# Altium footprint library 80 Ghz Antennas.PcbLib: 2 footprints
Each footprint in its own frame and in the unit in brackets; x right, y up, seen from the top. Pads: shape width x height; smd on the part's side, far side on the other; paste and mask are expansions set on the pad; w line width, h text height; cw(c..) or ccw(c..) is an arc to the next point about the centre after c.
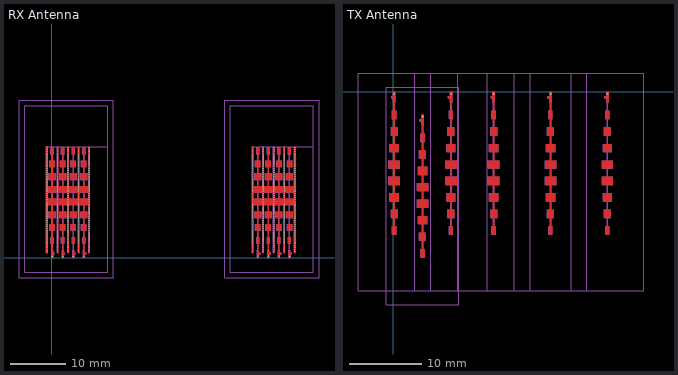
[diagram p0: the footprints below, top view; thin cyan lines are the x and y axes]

## RX Antenna [mm] "RX 80 Ghz Antenna"
pads (8):
  round 0.25 smd: "D1 - RX1"(0.139,0.25) "D1 - RX2"(2.039,0.25) "D1 - RX3"(3.939,0.25) "D1 - RX4"(5.839,0.25) "D2 - RX1"(37.189,0.25) "D2 - RX2"(39.089,0.25) "D2 - RX3"(40.989,0.25) "D2 - RX4"(42.889,0.25)
via 6.789,1.124 diameter 0.2 hole 0.1
via 6.789,1.499 diameter 0.2 hole 0.1
via 6.789,1.874 diameter 0.2 hole 0.1
via 6.789,2.249 diameter 0.2 hole 0.1
via 6.789,2.624 diameter 0.2 hole 0.1
via 6.789,2.999 diameter 0.2 hole 0.1
via 6.789,3.374 diameter 0.2 hole 0.1
via 6.789,5.624 diameter 0.2 hole 0.1
via 6.789,5.249 diameter 0.2 hole 0.1
via 6.789,4.874 diameter 0.2 hole 0.1
via 6.789,4.499 diameter 0.2 hole 0.1
via 6.789,4.124 diameter 0.2 hole 0.1
via 6.789,3.749 diameter 0.2 hole 0.1
via 6.789,7.874 diameter 0.2 hole 0.1
via 6.789,7.499 diameter 0.2 hole 0.1
via 6.789,7.124 diameter 0.2 hole 0.1
via 6.789,6.749 diameter 0.2 hole 0.1
via 6.789,6.374 diameter 0.2 hole 0.1
via 6.789,5.999 diameter 0.2 hole 0.1
via 6.789,10.124 diameter 0.2 hole 0.1
via 6.789,9.749 diameter 0.2 hole 0.1
via 6.789,9.374 diameter 0.2 hole 0.1
via 6.789,8.999 diameter 0.2 hole 0.1
via 6.789,8.624 diameter 0.2 hole 0.1
via 6.789,8.249 diameter 0.2 hole 0.1
via 6.789,12.374 diameter 0.2 hole 0.1
via 6.789,11.999 diameter 0.2 hole 0.1
via 6.789,11.624 diameter 0.2 hole 0.1
via 6.789,11.249 diameter 0.2 hole 0.1
via 6.789,10.874 diameter 0.2 hole 0.1
via 6.789,10.499 diameter 0.2 hole 0.1
via 6.789,14.624 diameter 0.2 hole 0.1
via 6.789,14.249 diameter 0.2 hole 0.1
via 6.789,13.874 diameter 0.2 hole 0.1
via 6.789,13.499 diameter 0.2 hole 0.1
via 6.789,13.124 diameter 0.2 hole 0.1
via 6.789,12.749 diameter 0.2 hole 0.1
via 6.789,16.874 diameter 0.2 hole 0.1
via 6.789,16.499 diameter 0.2 hole 0.1
via 6.789,16.124 diameter 0.2 hole 0.1
via 6.789,15.749 diameter 0.2 hole 0.1
via 6.789,15.374 diameter 0.2 hole 0.1
via 6.789,14.999 diameter 0.2 hole 0.1
via 6.789,19.124 diameter 0.2 hole 0.1
via 6.789,18.749 diameter 0.2 hole 0.1
via 6.789,18.374 diameter 0.2 hole 0.1
via 6.789,17.999 diameter 0.2 hole 0.1
via 6.789,17.624 diameter 0.2 hole 0.1
via 6.789,17.249 diameter 0.2 hole 0.1
via 6.789,19.499 diameter 0.2 hole 0.1
via 6.789,19.874 diameter 0.2 hole 0.1
via 4.889,1.124 diameter 0.2 hole 0.1
via 4.889,1.499 diameter 0.2 hole 0.1
via 4.889,1.874 diameter 0.2 hole 0.1
via 4.889,2.249 diameter 0.2 hole 0.1
via 4.889,2.624 diameter 0.2 hole 0.1
via 4.889,2.999 diameter 0.2 hole 0.1
via 4.889,3.374 diameter 0.2 hole 0.1
via 4.889,5.624 diameter 0.2 hole 0.1
via 4.889,5.249 diameter 0.2 hole 0.1
via 4.889,4.874 diameter 0.2 hole 0.1
via 4.889,4.499 diameter 0.2 hole 0.1
via 4.889,4.124 diameter 0.2 hole 0.1
via 4.889,3.749 diameter 0.2 hole 0.1
via 4.889,7.874 diameter 0.2 hole 0.1
via 4.889,7.499 diameter 0.2 hole 0.1
via 4.889,7.124 diameter 0.2 hole 0.1
via 4.889,6.749 diameter 0.2 hole 0.1
via 4.889,6.374 diameter 0.2 hole 0.1
via 4.889,5.999 diameter 0.2 hole 0.1
via 4.889,10.124 diameter 0.2 hole 0.1
via 4.889,9.749 diameter 0.2 hole 0.1
via 4.889,9.374 diameter 0.2 hole 0.1
via 4.889,8.999 diameter 0.2 hole 0.1
via 4.889,8.624 diameter 0.2 hole 0.1
via 4.889,8.249 diameter 0.2 hole 0.1
via 4.889,12.374 diameter 0.2 hole 0.1
via 4.889,11.999 diameter 0.2 hole 0.1
via 4.889,11.624 diameter 0.2 hole 0.1
via 4.889,11.249 diameter 0.2 hole 0.1
via 4.889,10.874 diameter 0.2 hole 0.1
via 4.889,10.499 diameter 0.2 hole 0.1
via 4.889,14.624 diameter 0.2 hole 0.1
via 4.889,14.249 diameter 0.2 hole 0.1
via 4.889,13.874 diameter 0.2 hole 0.1
via 4.889,13.499 diameter 0.2 hole 0.1
via 4.889,13.124 diameter 0.2 hole 0.1
via 4.889,12.749 diameter 0.2 hole 0.1
via 4.889,16.874 diameter 0.2 hole 0.1
via 4.889,16.499 diameter 0.2 hole 0.1
via 4.889,16.124 diameter 0.2 hole 0.1
via 4.889,15.749 diameter 0.2 hole 0.1
via 4.889,15.374 diameter 0.2 hole 0.1
via 4.889,14.999 diameter 0.2 hole 0.1
via 4.889,19.124 diameter 0.2 hole 0.1
via 4.889,18.749 diameter 0.2 hole 0.1
via 4.889,18.374 diameter 0.2 hole 0.1
via 4.889,17.999 diameter 0.2 hole 0.1
via 4.889,17.624 diameter 0.2 hole 0.1
via 4.889,17.249 diameter 0.2 hole 0.1
via 4.889,19.499 diameter 0.2 hole 0.1
via 4.889,19.874 diameter 0.2 hole 0.1
via 2.989,1.124 diameter 0.2 hole 0.1
via 2.989,1.499 diameter 0.2 hole 0.1
via 2.989,1.874 diameter 0.2 hole 0.1
via 2.989,2.249 diameter 0.2 hole 0.1
via 2.989,2.624 diameter 0.2 hole 0.1
via 2.989,2.999 diameter 0.2 hole 0.1
via 2.989,3.374 diameter 0.2 hole 0.1
via 2.989,5.624 diameter 0.2 hole 0.1
via 2.989,5.249 diameter 0.2 hole 0.1
via 2.989,4.874 diameter 0.2 hole 0.1
via 2.989,4.499 diameter 0.2 hole 0.1
via 2.989,4.124 diameter 0.2 hole 0.1
via 2.989,3.749 diameter 0.2 hole 0.1
via 2.989,7.874 diameter 0.2 hole 0.1
via 2.989,7.499 diameter 0.2 hole 0.1
via 2.989,7.124 diameter 0.2 hole 0.1
via 2.989,6.749 diameter 0.2 hole 0.1
via 2.989,6.374 diameter 0.2 hole 0.1
via 2.989,5.999 diameter 0.2 hole 0.1
via 2.989,8.999 diameter 0.2 hole 0.1
via 2.989,8.624 diameter 0.2 hole 0.1
via 2.989,8.249 diameter 0.2 hole 0.1
via 2.989,12.374 diameter 0.2 hole 0.1
via 2.989,11.999 diameter 0.2 hole 0.1
via 2.989,11.624 diameter 0.2 hole 0.1
via 2.989,11.249 diameter 0.2 hole 0.1
via 2.989,10.874 diameter 0.2 hole 0.1
via 2.989,10.499 diameter 0.2 hole 0.1
via 2.989,14.624 diameter 0.2 hole 0.1
via 2.989,14.249 diameter 0.2 hole 0.1
via 2.989,13.874 diameter 0.2 hole 0.1
via 2.989,13.499 diameter 0.2 hole 0.1
via 2.989,13.124 diameter 0.2 hole 0.1
via 2.989,12.749 diameter 0.2 hole 0.1
via 2.989,16.874 diameter 0.2 hole 0.1
via 2.989,16.499 diameter 0.2 hole 0.1
via 2.989,16.124 diameter 0.2 hole 0.1
via 2.989,15.749 diameter 0.2 hole 0.1
via 2.989,15.374 diameter 0.2 hole 0.1
via 2.989,14.999 diameter 0.2 hole 0.1
via 2.989,19.124 diameter 0.2 hole 0.1
via 2.989,18.749 diameter 0.2 hole 0.1
via 2.989,18.374 diameter 0.2 hole 0.1
via 2.989,17.999 diameter 0.2 hole 0.1
via 2.989,17.624 diameter 0.2 hole 0.1
via 2.989,17.249 diameter 0.2 hole 0.1
via 2.989,19.499 diameter 0.2 hole 0.1
via 2.989,19.874 diameter 0.2 hole 0.1
via 1.089,1.124 diameter 0.2 hole 0.1
via 1.089,1.499 diameter 0.2 hole 0.1
via 1.089,1.874 diameter 0.2 hole 0.1
via 1.089,2.249 diameter 0.2 hole 0.1
via 1.089,2.624 diameter 0.2 hole 0.1
via 1.089,2.999 diameter 0.2 hole 0.1
via 1.089,3.374 diameter 0.2 hole 0.1
via 1.089,5.624 diameter 0.2 hole 0.1
via 1.089,5.249 diameter 0.2 hole 0.1
via 1.089,4.874 diameter 0.2 hole 0.1
via 1.089,4.499 diameter 0.2 hole 0.1
via 1.089,4.124 diameter 0.2 hole 0.1
via 1.089,3.749 diameter 0.2 hole 0.1
via 1.089,7.874 diameter 0.2 hole 0.1
via 1.089,7.499 diameter 0.2 hole 0.1
via 1.089,7.124 diameter 0.2 hole 0.1
via 1.089,6.749 diameter 0.2 hole 0.1
via 1.089,6.374 diameter 0.2 hole 0.1
via 1.089,5.999 diameter 0.2 hole 0.1
via 1.089,10.124 diameter 0.2 hole 0.1
via 1.089,9.749 diameter 0.2 hole 0.1
via 1.089,9.374 diameter 0.2 hole 0.1
via 1.089,8.999 diameter 0.2 hole 0.1
via 1.089,8.624 diameter 0.2 hole 0.1
via 1.089,8.249 diameter 0.2 hole 0.1
via 1.089,12.374 diameter 0.2 hole 0.1
via 1.089,11.999 diameter 0.2 hole 0.1
via 1.089,11.624 diameter 0.2 hole 0.1
via 1.089,11.249 diameter 0.2 hole 0.1
via 1.089,10.874 diameter 0.2 hole 0.1
via 1.089,10.499 diameter 0.2 hole 0.1
via 1.089,14.624 diameter 0.2 hole 0.1
via 1.089,14.249 diameter 0.2 hole 0.1
via 1.089,13.874 diameter 0.2 hole 0.1
via 1.089,13.499 diameter 0.2 hole 0.1
via 1.089,13.124 diameter 0.2 hole 0.1
via 1.089,12.749 diameter 0.2 hole 0.1
via 1.089,16.874 diameter 0.2 hole 0.1
via 1.089,16.499 diameter 0.2 hole 0.1
via 1.089,16.124 diameter 0.2 hole 0.1
via 1.089,15.749 diameter 0.2 hole 0.1
via 1.089,15.374 diameter 0.2 hole 0.1
via 1.089,14.999 diameter 0.2 hole 0.1
via 1.089,19.124 diameter 0.2 hole 0.1
via 1.089,18.749 diameter 0.2 hole 0.1
via 1.089,18.374 diameter 0.2 hole 0.1
via 1.089,17.999 diameter 0.2 hole 0.1
via 1.089,17.624 diameter 0.2 hole 0.1
via 1.089,17.249 diameter 0.2 hole 0.1
via 1.089,19.499 diameter 0.2 hole 0.1
via 1.089,19.874 diameter 0.2 hole 0.1
via -0.811,19.874 diameter 0.2 hole 0.1
via -0.811,19.499 diameter 0.2 hole 0.1
via -0.811,17.249 diameter 0.2 hole 0.1
via -0.811,17.624 diameter 0.2 hole 0.1
via -0.811,17.999 diameter 0.2 hole 0.1
via -0.811,18.374 diameter 0.2 hole 0.1
via -0.811,18.749 diameter 0.2 hole 0.1
via -0.811,19.124 diameter 0.2 hole 0.1
via -0.811,14.999 diameter 0.2 hole 0.1
via -0.811,15.374 diameter 0.2 hole 0.1
via -0.811,15.749 diameter 0.2 hole 0.1
via -0.811,16.124 diameter 0.2 hole 0.1
via -0.811,16.499 diameter 0.2 hole 0.1
via -0.811,16.874 diameter 0.2 hole 0.1
via -0.811,12.749 diameter 0.2 hole 0.1
via -0.811,13.124 diameter 0.2 hole 0.1
via -0.811,13.499 diameter 0.2 hole 0.1
via -0.811,13.874 diameter 0.2 hole 0.1
via -0.811,14.249 diameter 0.2 hole 0.1
via -0.811,14.624 diameter 0.2 hole 0.1
via -0.811,10.499 diameter 0.2 hole 0.1
via -0.811,10.874 diameter 0.2 hole 0.1
via -0.811,11.249 diameter 0.2 hole 0.1
via -0.811,11.624 diameter 0.2 hole 0.1
via -0.811,11.999 diameter 0.2 hole 0.1
via -0.811,12.374 diameter 0.2 hole 0.1
via -0.811,8.249 diameter 0.2 hole 0.1
via -0.811,8.624 diameter 0.2 hole 0.1
via -0.811,8.999 diameter 0.2 hole 0.1
via -0.811,9.374 diameter 0.2 hole 0.1
via -0.811,9.749 diameter 0.2 hole 0.1
via -0.811,10.124 diameter 0.2 hole 0.1
via -0.811,5.999 diameter 0.2 hole 0.1
via -0.811,6.374 diameter 0.2 hole 0.1
via -0.811,6.749 diameter 0.2 hole 0.1
via -0.811,7.124 diameter 0.2 hole 0.1
via -0.811,7.499 diameter 0.2 hole 0.1
via -0.811,7.874 diameter 0.2 hole 0.1
via -0.811,3.749 diameter 0.2 hole 0.1
via -0.811,4.124 diameter 0.2 hole 0.1
via -0.811,4.499 diameter 0.2 hole 0.1
via -0.811,4.874 diameter 0.2 hole 0.1
via -0.811,5.249 diameter 0.2 hole 0.1
via -0.811,5.624 diameter 0.2 hole 0.1
via -0.811,3.374 diameter 0.2 hole 0.1
via -0.811,2.999 diameter 0.2 hole 0.1
via -0.811,2.624 diameter 0.2 hole 0.1
via -0.811,2.249 diameter 0.2 hole 0.1
via -0.811,1.874 diameter 0.2 hole 0.1
via -0.811,1.499 diameter 0.2 hole 0.1
via -0.811,1.124 diameter 0.2 hole 0.1
via 36.239,1.124 diameter 0.2 hole 0.1
via 36.239,1.499 diameter 0.2 hole 0.1
via 36.239,1.874 diameter 0.2 hole 0.1
via 36.239,2.249 diameter 0.2 hole 0.1
via 36.239,2.624 diameter 0.2 hole 0.1
via 36.239,2.999 diameter 0.2 hole 0.1
via 36.239,3.374 diameter 0.2 hole 0.1
via 36.239,5.624 diameter 0.2 hole 0.1
via 36.239,5.249 diameter 0.2 hole 0.1
via 36.239,4.874 diameter 0.2 hole 0.1
via 36.239,4.499 diameter 0.2 hole 0.1
via 36.239,4.124 diameter 0.2 hole 0.1
via 36.239,3.749 diameter 0.2 hole 0.1
via 36.239,7.874 diameter 0.2 hole 0.1
via 36.239,7.499 diameter 0.2 hole 0.1
via 36.239,7.124 diameter 0.2 hole 0.1
via 36.239,6.749 diameter 0.2 hole 0.1
via 36.239,6.374 diameter 0.2 hole 0.1
via 36.239,5.999 diameter 0.2 hole 0.1
via 36.239,10.124 diameter 0.2 hole 0.1
via 36.239,9.749 diameter 0.2 hole 0.1
via 36.239,9.374 diameter 0.2 hole 0.1
via 36.239,8.999 diameter 0.2 hole 0.1
via 36.239,8.624 diameter 0.2 hole 0.1
via 36.239,8.249 diameter 0.2 hole 0.1
via 36.239,12.374 diameter 0.2 hole 0.1
via 36.239,11.999 diameter 0.2 hole 0.1
via 36.239,11.624 diameter 0.2 hole 0.1
via 36.239,11.249 diameter 0.2 hole 0.1
via 36.239,10.874 diameter 0.2 hole 0.1
via 36.239,10.499 diameter 0.2 hole 0.1
via 36.239,14.624 diameter 0.2 hole 0.1
via 36.239,14.249 diameter 0.2 hole 0.1
via 36.239,13.874 diameter 0.2 hole 0.1
via 36.239,13.499 diameter 0.2 hole 0.1
via 36.239,13.124 diameter 0.2 hole 0.1
via 36.239,12.749 diameter 0.2 hole 0.1
via 36.239,16.874 diameter 0.2 hole 0.1
via 36.239,16.499 diameter 0.2 hole 0.1
via 36.239,16.124 diameter 0.2 hole 0.1
via 36.239,15.749 diameter 0.2 hole 0.1
via 36.239,15.374 diameter 0.2 hole 0.1
via 36.239,14.999 diameter 0.2 hole 0.1
via 36.239,19.124 diameter 0.2 hole 0.1
via 36.239,18.749 diameter 0.2 hole 0.1
via 36.239,18.374 diameter 0.2 hole 0.1
via 36.239,17.999 diameter 0.2 hole 0.1
via 36.239,17.624 diameter 0.2 hole 0.1
via 36.239,17.249 diameter 0.2 hole 0.1
via 36.239,19.499 diameter 0.2 hole 0.1
via 36.239,19.874 diameter 0.2 hole 0.1
via 38.139,1.124 diameter 0.2 hole 0.1
via 38.139,1.499 diameter 0.2 hole 0.1
via 38.139,1.874 diameter 0.2 hole 0.1
via 38.139,2.249 diameter 0.2 hole 0.1
via 38.139,2.624 diameter 0.2 hole 0.1
via 38.139,2.999 diameter 0.2 hole 0.1
via 38.139,3.374 diameter 0.2 hole 0.1
via 38.139,5.624 diameter 0.2 hole 0.1
via 38.139,5.249 diameter 0.2 hole 0.1
via 38.139,4.874 diameter 0.2 hole 0.1
via 38.139,4.499 diameter 0.2 hole 0.1
via 38.139,4.124 diameter 0.2 hole 0.1
via 38.139,3.749 diameter 0.2 hole 0.1
via 38.139,7.874 diameter 0.2 hole 0.1
via 38.139,7.499 diameter 0.2 hole 0.1
via 38.139,7.124 diameter 0.2 hole 0.1
via 38.139,6.749 diameter 0.2 hole 0.1
via 38.139,6.374 diameter 0.2 hole 0.1
via 38.139,5.999 diameter 0.2 hole 0.1
via 38.139,10.124 diameter 0.2 hole 0.1
via 38.139,9.749 diameter 0.2 hole 0.1
via 38.139,9.374 diameter 0.2 hole 0.1
via 38.139,8.999 diameter 0.2 hole 0.1
via 38.139,8.624 diameter 0.2 hole 0.1
via 38.139,8.249 diameter 0.2 hole 0.1
via 38.139,12.374 diameter 0.2 hole 0.1
via 38.139,11.999 diameter 0.2 hole 0.1
via 38.139,11.624 diameter 0.2 hole 0.1
via 38.139,11.249 diameter 0.2 hole 0.1
via 38.139,10.874 diameter 0.2 hole 0.1
via 38.139,10.499 diameter 0.2 hole 0.1
via 38.139,14.624 diameter 0.2 hole 0.1
via 38.139,14.249 diameter 0.2 hole 0.1
via 38.139,13.874 diameter 0.2 hole 0.1
via 38.139,13.499 diameter 0.2 hole 0.1
via 38.139,13.124 diameter 0.2 hole 0.1
via 38.139,12.749 diameter 0.2 hole 0.1
via 38.139,16.874 diameter 0.2 hole 0.1
via 38.139,16.499 diameter 0.2 hole 0.1
via 38.139,16.124 diameter 0.2 hole 0.1
via 38.139,15.749 diameter 0.2 hole 0.1
via 38.139,15.374 diameter 0.2 hole 0.1
via 38.139,14.999 diameter 0.2 hole 0.1
via 38.139,19.124 diameter 0.2 hole 0.1
via 38.139,18.749 diameter 0.2 hole 0.1
via 38.139,18.374 diameter 0.2 hole 0.1
via 38.139,17.999 diameter 0.2 hole 0.1
via 38.139,17.624 diameter 0.2 hole 0.1
via 38.139,17.249 diameter 0.2 hole 0.1
via 38.139,19.499 diameter 0.2 hole 0.1
via 38.139,19.874 diameter 0.2 hole 0.1
via 40.039,1.124 diameter 0.2 hole 0.1
via 40.039,1.499 diameter 0.2 hole 0.1
via 40.039,1.874 diameter 0.2 hole 0.1
via 40.039,2.249 diameter 0.2 hole 0.1
via 40.039,2.624 diameter 0.2 hole 0.1
via 40.039,2.999 diameter 0.2 hole 0.1
via 40.039,3.374 diameter 0.2 hole 0.1
via 40.039,5.624 diameter 0.2 hole 0.1
via 40.039,5.249 diameter 0.2 hole 0.1
via 40.039,4.874 diameter 0.2 hole 0.1
via 40.039,4.499 diameter 0.2 hole 0.1
via 40.039,4.124 diameter 0.2 hole 0.1
via 40.039,3.749 diameter 0.2 hole 0.1
via 40.039,7.874 diameter 0.2 hole 0.1
via 40.039,7.499 diameter 0.2 hole 0.1
via 40.039,7.124 diameter 0.2 hole 0.1
via 40.039,6.749 diameter 0.2 hole 0.1
via 40.039,6.374 diameter 0.2 hole 0.1
via 40.039,5.999 diameter 0.2 hole 0.1
via 40.039,10.124 diameter 0.2 hole 0.1
via 40.039,9.749 diameter 0.2 hole 0.1
via 40.039,9.374 diameter 0.2 hole 0.1
via 40.039,8.999 diameter 0.2 hole 0.1
via 40.039,8.624 diameter 0.2 hole 0.1
via 40.039,8.249 diameter 0.2 hole 0.1
via 40.039,12.374 diameter 0.2 hole 0.1
via 40.039,11.999 diameter 0.2 hole 0.1
via 40.039,11.624 diameter 0.2 hole 0.1
via 40.039,11.249 diameter 0.2 hole 0.1
via 40.039,10.874 diameter 0.2 hole 0.1
via 40.039,10.499 diameter 0.2 hole 0.1
via 40.039,14.624 diameter 0.2 hole 0.1
via 40.039,14.249 diameter 0.2 hole 0.1
via 40.039,13.874 diameter 0.2 hole 0.1
via 40.039,13.499 diameter 0.2 hole 0.1
via 40.039,13.124 diameter 0.2 hole 0.1
via 40.039,12.749 diameter 0.2 hole 0.1
via 40.039,16.874 diameter 0.2 hole 0.1
via 40.039,16.499 diameter 0.2 hole 0.1
via 40.039,16.124 diameter 0.2 hole 0.1
via 40.039,15.749 diameter 0.2 hole 0.1
via 40.039,15.374 diameter 0.2 hole 0.1
via 40.039,14.999 diameter 0.2 hole 0.1
via 40.039,19.124 diameter 0.2 hole 0.1
via 40.039,18.749 diameter 0.2 hole 0.1
via 40.039,18.374 diameter 0.2 hole 0.1
via 40.039,17.999 diameter 0.2 hole 0.1
via 40.039,17.624 diameter 0.2 hole 0.1
via 40.039,17.249 diameter 0.2 hole 0.1
via 40.039,19.499 diameter 0.2 hole 0.1
via 40.039,19.874 diameter 0.2 hole 0.1
via 41.939,1.124 diameter 0.2 hole 0.1
via 41.939,1.499 diameter 0.2 hole 0.1
via 41.939,1.874 diameter 0.2 hole 0.1
via 41.939,2.249 diameter 0.2 hole 0.1
via 41.939,2.624 diameter 0.2 hole 0.1
via 41.939,2.999 diameter 0.2 hole 0.1
via 41.939,3.374 diameter 0.2 hole 0.1
via 41.939,5.624 diameter 0.2 hole 0.1
via 41.939,5.249 diameter 0.2 hole 0.1
via 41.939,4.874 diameter 0.2 hole 0.1
via 41.939,4.499 diameter 0.2 hole 0.1
via 41.939,4.124 diameter 0.2 hole 0.1
via 41.939,3.749 diameter 0.2 hole 0.1
via 41.939,7.874 diameter 0.2 hole 0.1
via 41.939,7.499 diameter 0.2 hole 0.1
via 41.939,7.124 diameter 0.2 hole 0.1
via 41.939,6.749 diameter 0.2 hole 0.1
via 41.939,6.374 diameter 0.2 hole 0.1
via 41.939,5.999 diameter 0.2 hole 0.1
via 41.939,10.124 diameter 0.2 hole 0.1
via 41.939,9.749 diameter 0.2 hole 0.1
via 41.939,9.374 diameter 0.2 hole 0.1
via 41.939,8.999 diameter 0.2 hole 0.1
via 41.939,8.624 diameter 0.2 hole 0.1
via 41.939,8.249 diameter 0.2 hole 0.1
via 41.939,12.374 diameter 0.2 hole 0.1
via 41.939,11.999 diameter 0.2 hole 0.1
via 41.939,11.624 diameter 0.2 hole 0.1
via 41.939,11.249 diameter 0.2 hole 0.1
via 41.939,10.874 diameter 0.2 hole 0.1
via 41.939,10.499 diameter 0.2 hole 0.1
via 41.939,14.624 diameter 0.2 hole 0.1
via 41.939,14.249 diameter 0.2 hole 0.1
via 41.939,13.874 diameter 0.2 hole 0.1
via 41.939,13.499 diameter 0.2 hole 0.1
via 41.939,13.124 diameter 0.2 hole 0.1
via 41.939,12.749 diameter 0.2 hole 0.1
via 41.939,16.874 diameter 0.2 hole 0.1
via 41.939,16.499 diameter 0.2 hole 0.1
via 41.939,16.124 diameter 0.2 hole 0.1
via 41.939,15.749 diameter 0.2 hole 0.1
via 41.939,15.374 diameter 0.2 hole 0.1
via 41.939,14.999 diameter 0.2 hole 0.1
via 41.939,19.124 diameter 0.2 hole 0.1
via 41.939,18.749 diameter 0.2 hole 0.1
via 41.939,18.374 diameter 0.2 hole 0.1
via 41.939,17.999 diameter 0.2 hole 0.1
via 41.939,17.624 diameter 0.2 hole 0.1
via 41.939,17.249 diameter 0.2 hole 0.1
via 41.939,19.499 diameter 0.2 hole 0.1
via 41.939,19.874 diameter 0.2 hole 0.1
via 43.839,1.124 diameter 0.2 hole 0.1
via 43.839,1.499 diameter 0.2 hole 0.1
via 43.839,1.874 diameter 0.2 hole 0.1
via 43.839,2.249 diameter 0.2 hole 0.1
via 43.839,2.624 diameter 0.2 hole 0.1
via 43.839,2.999 diameter 0.2 hole 0.1
via 43.839,3.374 diameter 0.2 hole 0.1
via 43.839,5.624 diameter 0.2 hole 0.1
via 43.839,5.249 diameter 0.2 hole 0.1
via 43.839,4.874 diameter 0.2 hole 0.1
via 43.839,4.499 diameter 0.2 hole 0.1
via 43.839,4.124 diameter 0.2 hole 0.1
via 43.839,3.749 diameter 0.2 hole 0.1
via 43.839,7.874 diameter 0.2 hole 0.1
via 43.839,7.499 diameter 0.2 hole 0.1
via 43.839,7.124 diameter 0.2 hole 0.1
via 43.839,6.749 diameter 0.2 hole 0.1
via 43.839,6.374 diameter 0.2 hole 0.1
via 43.839,5.999 diameter 0.2 hole 0.1
via 43.839,10.124 diameter 0.2 hole 0.1
via 43.839,9.749 diameter 0.2 hole 0.1
via 43.839,9.374 diameter 0.2 hole 0.1
via 43.839,8.999 diameter 0.2 hole 0.1
via 43.839,8.624 diameter 0.2 hole 0.1
via 43.839,8.249 diameter 0.2 hole 0.1
via 43.839,12.374 diameter 0.2 hole 0.1
via 43.839,11.999 diameter 0.2 hole 0.1
via 43.839,11.624 diameter 0.2 hole 0.1
via 43.839,11.249 diameter 0.2 hole 0.1
via 43.839,10.874 diameter 0.2 hole 0.1
via 43.839,10.499 diameter 0.2 hole 0.1
via 43.839,14.624 diameter 0.2 hole 0.1
via 43.839,14.249 diameter 0.2 hole 0.1
via 43.839,13.874 diameter 0.2 hole 0.1
via 43.839,13.499 diameter 0.2 hole 0.1
via 43.839,13.124 diameter 0.2 hole 0.1
via 43.839,12.749 diameter 0.2 hole 0.1
via 43.839,16.874 diameter 0.2 hole 0.1
via 43.839,16.499 diameter 0.2 hole 0.1
via 43.839,16.124 diameter 0.2 hole 0.1
via 43.839,15.749 diameter 0.2 hole 0.1
via 43.839,15.374 diameter 0.2 hole 0.1
via 43.839,14.999 diameter 0.2 hole 0.1
via 43.839,19.124 diameter 0.2 hole 0.1
via 43.839,18.749 diameter 0.2 hole 0.1
via 43.839,18.374 diameter 0.2 hole 0.1
via 43.839,17.999 diameter 0.2 hole 0.1
via 43.839,17.624 diameter 0.2 hole 0.1
via 43.839,17.249 diameter 0.2 hole 0.1
via 43.839,19.499 diameter 0.2 hole 0.1
via 43.839,19.874 diameter 0.2 hole 0.1
via 2.989,10.124 diameter 0.2 hole 0.1
via 2.989,9.749 diameter 0.2 hole 0.1
via 2.989,9.374 diameter 0.2 hole 0.1
Top Layer:
  region: 6.689,0.951 6.889,0.951 6.889,20.046 6.689,20.046
  region: 4.789,0.951 4.989,0.951 4.989,20.046 4.789,20.046
  region: 2.889,0.951 3.089,0.951 3.089,20.046 2.889,20.046
  region: 0.989,0.951 1.189,0.951 1.189,20.046 0.989,20.046
  region: -0.911,0.951 -0.711,0.951 -0.711,20.046 -0.911,20.046
  region: 1.9,0 1.9,1.4 1.989,1.4 1.989,2.6 1.789,2.6 1.789,3.725 1.989,3.725 1.989,4.925 1.589,4.925 1.589,6.035 1.989,6.035 1.989,7.235 1.439,7.235 1.439,8.33 1.989,8.33 1.989,9.53 1.289,9.53 1.289,10.615 1.989,10.615 1.989,11.815 1.289,11.815 1.289,12.9 1.989,12.9 1.989,14.1 1.439,14.1 1.439,15.195 1.989,15.195 1.989,16.395 1.589,16.395 1.589,17.505 1.989,17.505 1.989,18.705 1.789,18.705 1.789,19.83 2.289,19.83 2.289,18.705 2.089,18.705 2.089,17.505 2.489,17.505 2.489,16.395 2.089,16.395 2.089,15.195 2.639,15.195 2.639,14.1 2.089,14.1 2.089,12.9 2.789,12.9 2.789,11.815 2.089,11.815 2.089,10.615 2.789,10.615 2.789,9.53 2.089,9.53 2.089,8.33 2.639,8.33 2.639,7.235 2.089,7.235 2.089,6.035 2.489,6.035 2.489,4.925 2.089,4.925 2.089,3.725 2.289,3.725 2.289,2.6 2.089,2.6 2.089,1.4 2.177,1.4 2.177,0.885 2.417,0.885 2.417,0.608 2.177,0.608 2.177,0
  region: 42.75,0 42.75,1.4 42.839,1.4 42.839,2.6 42.639,2.6 42.639,3.725 42.839,3.725 42.839,4.925 42.439,4.925 42.439,6.035 42.839,6.035 42.839,7.235 42.289,7.235 42.289,8.33 42.839,8.33 42.839,9.53 42.139,9.53 42.139,10.615 42.839,10.615 42.839,11.815 42.139,11.815 42.139,12.9 42.839,12.9 42.839,14.1 42.289,14.1 42.289,15.195 42.839,15.195 42.839,16.395 42.439,16.395 42.439,17.505 42.839,17.505 42.839,18.705 42.639,18.705 42.639,19.83 43.139,19.83 43.139,18.705 42.939,18.705 42.939,17.505 43.339,17.505 43.339,16.395 42.939,16.395 42.939,15.195 43.489,15.195 43.489,14.1 42.939,14.1 42.939,12.9 43.639,12.9 43.639,11.815 42.939,11.815 42.939,10.615 43.639,10.615 43.639,9.53 42.939,9.53 42.939,8.33 43.489,8.33 43.489,7.235 42.939,7.235 42.939,6.035 43.339,6.035 43.339,4.925 42.939,4.925 42.939,3.725 43.139,3.725 43.139,2.6 42.939,2.6 42.939,1.4 43.027,1.4 43.027,0.885 43.267,0.885 43.267,0.608 43.027,0.608 43.027,0
  region: 38.95,0 38.95,1.4 39.039,1.4 39.039,2.6 38.839,2.6 38.839,3.725 39.039,3.725 39.039,4.925 38.639,4.925 38.639,6.035 39.039,6.035 39.039,7.235 38.489,7.235 38.489,8.33 39.039,8.33 39.039,9.53 38.339,9.53 38.339,10.615 39.039,10.615 39.039,11.815 38.339,11.815 38.339,12.9 39.039,12.9 39.039,14.1 38.489,14.1 38.489,15.195 39.039,15.195 39.039,16.395 38.639,16.395 38.639,17.505 39.039,17.505 39.039,18.705 38.839,18.705 38.839,19.83 39.339,19.83 39.339,18.705 39.139,18.705 39.139,17.505 39.539,17.505 39.539,16.395 39.139,16.395 39.139,15.195 39.689,15.195 39.689,14.1 39.139,14.1 39.139,12.9 39.839,12.9 39.839,11.815 39.139,11.815 39.139,10.615 39.839,10.615 39.839,9.53 39.139,9.53 39.139,8.33 39.689,8.33 39.689,7.235 39.139,7.235 39.139,6.035 39.539,6.035 39.539,4.925 39.139,4.925 39.139,3.725 39.339,3.725 39.339,2.6 39.139,2.6 39.139,1.4 39.227,1.4 39.227,0.885 39.467,0.885 39.467,0.608 39.227,0.608 39.227,0
  region: 37.05,0 37.05,1.4 37.139,1.4 37.139,2.6 36.939,2.6 36.939,3.725 37.139,3.725 37.139,4.925 36.739,4.925 36.739,6.035 37.139,6.035 37.139,7.235 36.589,7.235 36.589,8.33 37.139,8.33 37.139,9.53 36.438,9.53 36.438,10.615 37.139,10.615 37.139,11.815 36.438,11.815 36.438,12.9 37.139,12.9 37.139,14.1 36.589,14.1 36.589,15.195 37.139,15.195 37.139,16.395 36.739,16.395 36.739,17.505 37.139,17.505 37.139,18.705 36.939,18.705 36.939,19.83 37.439,19.83 37.439,18.705 37.239,18.705 37.239,17.505 37.638,17.505 37.638,16.395 37.239,16.395 37.239,15.195 37.788,15.195 37.788,14.1 37.239,14.1 37.239,12.9 37.939,12.9 37.939,11.815 37.239,11.815 37.239,10.615 37.939,10.615 37.939,9.53 37.239,9.53 37.239,8.33 37.788,8.33 37.788,7.235 37.239,7.235 37.239,6.035 37.638,6.035 37.638,4.925 37.239,4.925 37.239,3.725 37.439,3.725 37.439,2.6 37.239,2.6 37.239,1.4 37.327,1.4 37.327,0.885 37.567,0.885 37.567,0.608 37.327,0.608 37.327,0
  region: 0,0 0,1.4 0.089,1.4 0.089,2.6 -0.111,2.6 -0.111,3.725 0.089,3.725 0.089,4.925 -0.311,4.925 -0.311,6.035 0.089,6.035 0.089,7.235 -0.461,7.235 -0.461,8.33 0.089,8.33 0.089,9.53 -0.611,9.53 -0.611,10.615 0.089,10.615 0.089,11.815 -0.611,11.815 -0.611,12.9 0.089,12.9 0.089,14.1 -0.461,14.1 -0.461,15.195 0.089,15.195 0.089,16.395 -0.311,16.395 -0.311,17.505 0.089,17.505 0.089,18.705 -0.111,18.705 -0.111,19.83 0.389,19.83 0.389,18.705 0.189,18.705 0.189,17.505 0.589,17.505 0.589,16.395 0.189,16.395 0.189,15.195 0.738,15.195 0.738,14.1 0.189,14.1 0.189,12.9 0.889,12.9 0.889,11.815 0.189,11.815 0.189,10.615 0.889,10.615 0.889,9.53 0.189,9.53 0.189,8.33 0.738,8.33 0.738,7.235 0.189,7.235 0.189,6.035 0.589,6.035 0.589,4.925 0.189,4.925 0.189,3.725 0.389,3.725 0.389,2.6 0.189,2.6 0.189,1.4 0.277,1.4 0.277,0.885 0.517,0.885 0.517,0.608 0.277,0.608 0.277,0
  region: 3.8,0 3.8,1.4 3.889,1.4 3.889,2.6 3.689,2.6 3.689,3.725 3.889,3.725 3.889,4.925 3.489,4.925 3.489,6.035 3.889,6.035 3.889,7.235 3.339,7.235 3.339,8.33 3.889,8.33 3.889,9.53 3.189,9.53 3.189,10.615 3.889,10.615 3.889,11.815 3.189,11.815 3.189,12.9 3.889,12.9 3.889,14.1 3.339,14.1 3.339,15.195 3.889,15.195 3.889,16.395 3.489,16.395 3.489,17.505 3.889,17.505 3.889,18.705 3.689,18.705 3.689,19.83 4.189,19.83 4.189,18.705 3.989,18.705 3.989,17.505 4.389,17.505 4.389,16.395 3.989,16.395 3.989,15.195 4.538,15.195 4.538,14.1 3.989,14.1 3.989,12.9 4.689,12.9 4.689,11.815 3.989,11.815 3.989,10.615 4.689,10.615 4.689,9.53 3.989,9.53 3.989,8.33 4.538,8.33 4.538,7.235 3.989,7.235 3.989,6.035 4.389,6.035 4.389,4.925 3.989,4.925 3.989,3.725 4.189,3.725 4.189,2.6 3.989,2.6 3.989,1.4 4.077,1.4 4.077,0.885 4.317,0.885 4.317,0.608 4.077,0.608 4.077,0
  region: 5.7,0 5.7,1.4 5.789,1.4 5.789,2.6 5.589,2.6 5.589,3.725 5.789,3.725 5.789,4.925 5.389,4.925 5.389,6.035 5.789,6.035 5.789,7.235 5.239,7.235 5.239,8.33 5.789,8.33 5.789,9.53 5.089,9.53 5.089,10.615 5.789,10.615 5.789,11.815 5.089,11.815 5.089,12.9 5.789,12.9 5.789,14.1 5.239,14.1 5.239,15.195 5.789,15.195 5.789,16.395 5.389,16.395 5.389,17.505 5.789,17.505 5.789,18.705 5.589,18.705 5.589,19.83 6.089,19.83 6.089,18.705 5.889,18.705 5.889,17.505 6.289,17.505 6.289,16.395 5.889,16.395 5.889,15.195 6.439,15.195 6.439,14.1 5.889,14.1 5.889,12.9 6.589,12.9 6.589,11.815 5.889,11.815 5.889,10.615 6.589,10.615 6.589,9.53 5.889,9.53 5.889,8.33 6.439,8.33 6.439,7.235 5.889,7.235 5.889,6.035 6.289,6.035 6.289,4.925 5.889,4.925 5.889,3.725 6.089,3.725 6.089,2.6 5.889,2.6 5.889,1.4 5.977,1.4 5.977,0.885 6.217,0.885 6.217,0.608 5.977,0.608 5.977,0
  region: 36.139,0.951 36.338,0.951 36.338,20.046 36.139,20.046
  region: 38.039,0.951 38.239,0.951 38.239,20.046 38.039,20.046
  region: 39.939,0.951 40.138,0.951 40.138,20.046 39.939,20.046
  region: 41.839,0.951 42.039,0.951 42.039,20.046 41.839,20.046
  region: 43.739,0.951 43.938,0.951 43.938,20.046 43.739,20.046
  region: 40.85,0 40.85,1.4 40.939,1.4 40.939,2.6 40.739,2.6 40.739,3.725 40.939,3.725 40.939,4.925 40.539,4.925 40.539,6.035 40.939,6.035 40.939,7.235 40.389,7.235 40.389,8.33 40.939,8.33 40.939,9.53 40.238,9.53 40.238,10.615 40.939,10.615 40.939,11.815 40.238,11.815 40.238,12.9 40.939,12.9 40.939,14.1 40.389,14.1 40.389,15.195 40.939,15.195 40.939,16.395 40.539,16.395 40.539,17.505 40.939,17.505 40.939,18.705 40.739,18.705 40.739,19.83 41.239,19.83 41.239,18.705 41.039,18.705 41.039,17.505 41.438,17.505 41.438,16.395 41.039,16.395 41.039,15.195 41.588,15.195 41.588,14.1 41.039,14.1 41.039,12.9 41.739,12.9 41.739,11.815 41.039,11.815 41.039,10.615 41.739,10.615 41.739,9.53 41.039,9.53 41.039,8.33 41.588,8.33 41.588,7.235 41.039,7.235 41.039,6.035 41.438,6.035 41.438,4.925 41.039,4.925 41.039,3.725 41.239,3.725 41.239,2.6 41.039,2.6 41.039,1.4 41.127,1.4 41.127,0.885 41.367,0.885 41.367,0.608 41.127,0.608 41.127,0
Top Solder:
  region: -5.861,-3.6 11.139,-3.6 11.139,28.4 -5.861,28.4
  region: 31.188,-3.6 48.189,-3.6 48.189,28.4 31.188,28.4
Mechanical 2:
  drawing of 576 lines, arcs and shapes, not listed
Mechanical 3:
  lines w0.013: -0.911,0.951 -0.911,20.046 ; -0.911,0.951 -0.711,0.951 ; -0.911,0.951 -0.911,20.046 ; -0.911,0.951 -0.711,0.951 ; -0.911,20.046 -0.711,20.046 ; -0.911,20.046 -0.711,20.046 ; -0.711,0.951 -0.711,20.046 ; -0.711,0.951 -0.711,20.046 ; 0.989,0.951 0.989,20.046 ; 0.989,0.951 1.189,0.951 ; 0.989,0.951 0.989,20.046 ; 0.989,0.951 1.189,0.951 ; 0.989,20.046 1.189,20.046 ; 0.989,20.046 1.189,20.046 ; 1.189,0.951 1.189,20.046 ; 1.189,0.951 1.189,20.046 ; 2.889,0.951 2.889,20.046 ; 2.889,0.951 3.089,0.951 ; 2.889,0.951 2.889,20.046 ; 2.889,0.951 3.089,0.951 ; 2.889,20.046 3.089,20.046 ; 2.889,20.046 3.089,20.046 ; 3.089,0.951 3.089,20.046 ; 3.089,0.951 3.089,20.046 ; 4.789,0.951 4.789,20.046 ; 4.789,0.951 4.989,0.951 ; 4.789,0.951 4.789,20.046 ; 4.789,0.951 4.989,0.951 ; 4.789,20.046 4.989,20.046 ; 4.789,20.046 4.989,20.046 ; 4.989,0.951 4.989,20.046 ; 4.989,0.951 4.989,20.046 ; 6.689,0.951 6.689,20.046 ; 6.689,0.951 6.889,0.951 ; 6.689,0.951 6.689,20.046 ; 6.689,0.951 6.889,0.951 ; 6.689,20.046 6.889,20.046 ; 6.689,20.046 6.889,20.046 ; 6.889,0.951 6.889,20.046 ; 6.889,0.951 6.889,20.046 ; 36.139,0.951 36.139,20.046 ; 36.139,0.951 36.338,0.951 ; 36.139,0.951 36.338,0.951 ; 36.139,0.951 36.139,20.046 ; 36.139,20.046 36.338,20.046 ; 36.139,20.046 36.338,20.046 ; 36.338,0.951 36.338,20.046 ; 36.338,0.951 36.338,20.046 ; 38.039,0.951 38.039,20.046 ; 38.039,0.951 38.239,0.951 ; 38.039,0.951 38.239,0.951 ; 38.039,0.951 38.039,20.046 ; 38.039,20.046 38.239,20.046 ; 38.039,20.046 38.239,20.046 ; 38.239,0.951 38.239,20.046 ; 38.239,0.951 38.239,20.046 ; 39.939,0.951 39.939,20.046 ; 39.939,0.951 40.138,0.951 ; 39.939,0.951 40.138,0.951 ; 39.939,0.951 39.939,20.046 ; 39.939,20.046 40.138,20.046 ; 39.939,20.046 40.138,20.046 ; 40.138,0.951 40.138,20.046 ; 40.138,0.951 40.138,20.046 ; 41.839,0.951 41.839,20.046 ; 41.839,0.951 42.039,0.951 ; 41.839,0.951 42.039,0.951 ; 41.839,0.951 41.839,20.046 ; 41.839,20.046 42.039,20.046 ; 41.839,20.046 42.039,20.046 ; 42.039,0.951 42.039,20.046 ; 42.039,0.951 42.039,20.046 ; 43.739,0.951 43.739,20.046 ; 43.739,0.951 43.938,0.951 ; 43.739,0.951 43.938,0.951 ; 43.739,0.951 43.739,20.046 ; 43.739,20.046 43.938,20.046 ; 43.739,20.046 43.938,20.046 ; 43.938,0.951 43.938,20.046 ; 43.938,0.951 43.938,20.046
Mechanical 5:
  lines w0.013: -0.911,0.951 -0.711,0.951 ; -0.911,0.951 -0.911,20.046 ; -0.911,0.951 -0.911,20.046 ; -0.911,0.951 -0.711,0.951 ; -0.911,20.046 -0.711,20.046 ; -0.911,20.046 -0.711,20.046 ; -0.711,0.951 -0.711,20.046 ; -0.711,0.951 -0.711,20.046 ; -0.711,20.046 0.989,20.046 ; 0.989,0.951 0.989,20.046 ; 0.989,0.951 1.189,0.951 ; 0.989,0.951 0.989,20.046 ; 0.989,0.951 1.189,0.951 ; 0.989,20.046 1.189,20.046 ; 0.989,20.046 1.189,20.046 ; 1.189,0.951 1.189,20.046 ; 1.189,0.951 1.189,20.046 ; 1.189,20.046 2.889,20.046 ; 2.889,0.951 3.089,0.951 ; 2.889,0.951 2.889,20.046 ; 2.889,0.951 3.089,0.951 ; 2.889,0.951 2.889,20.046 ; 2.889,20.046 3.089,20.046 ; 2.889,20.046 3.089,20.046 ; 3.089,0.951 3.089,20.046 ; 3.089,0.951 3.089,20.046 ; 3.089,20.046 4.789,20.046 ; 4.789,0.951 4.989,0.951 ; 4.789,0.951 4.789,20.046 ; 4.789,0.951 4.789,20.046 ; 4.789,0.951 4.989,0.951 ; 4.789,20.046 4.989,20.046 ; 4.789,20.046 4.989,20.046 ; 4.989,0.951 4.989,20.046 ; 4.989,0.951 4.989,20.046 ; 4.989,20.046 6.689,20.046 ; 6.689,0.951 6.689,20.046 ; 6.689,0.951 6.889,0.951 ; 6.689,0.951 6.889,0.951 ; 6.689,0.951 6.689,20.046 ; 6.689,20.046 6.889,20.046 ; 6.689,20.046 6.889,20.046 ; 6.889,0.951 6.889,20.046 ; 6.889,0.951 6.889,20.046 ; 6.889,20.046 10.139,20.046 ; 10.139,20.046 10.139,27.4 -4.861,27.4 -4.861,-2.6 10.139,-2.6 10.139,20.046 ; 36.139,0.951 36.338,0.951 ; 36.139,0.951 36.139,20.046 ; 36.139,0.951 36.139,20.046 ; 36.139,0.951 36.338,0.951 ; 36.139,20.046 36.338,20.046 ; 36.139,20.046 36.338,20.046 ; 36.338,0.951 36.338,20.046 ; 36.338,0.951 36.338,20.046 ; 36.338,20.046 38.039,20.046 ; 38.039,0.951 38.239,0.951 ; 38.039,0.951 38.039,20.046 ; 38.039,0.951 38.039,20.046 ; 38.039,0.951 38.239,0.951 ; 38.039,20.046 38.239,20.046 ; 38.039,20.046 38.239,20.046 ; 38.239,0.951 38.239,20.046 ; 38.239,0.951 38.239,20.046 ; 38.239,20.046 39.939,20.046 ; 39.939,0.951 40.138,0.951 ; 39.939,0.951 39.939,20.046 ; 39.939,0.951 39.939,20.046 ; 39.939,0.951 40.138,0.951 ; 39.939,20.046 40.138,20.046 ; 39.939,20.046 40.138,20.046 ; 40.138,0.951 40.138,20.046 ; 40.138,0.951 40.138,20.046 ; 40.138,20.046 41.839,20.046 ; 41.839,0.951 42.039,0.951 ; 41.839,0.951 41.839,20.046 ; 41.839,0.951 41.839,20.046 ; 41.839,0.951 42.039,0.951 ; 41.839,20.046 42.039,20.046 ; 41.839,20.046 42.039,20.046 ; 42.039,0.951 42.039,20.046 ; 42.039,0.951 42.039,20.046 ; 42.039,20.046 43.739,20.046 ; 43.739,0.951 43.938,0.951 ; 43.739,0.951 43.739,20.046 ; 43.739,0.951 43.739,20.046 ; 43.739,0.951 43.938,0.951 ; 43.739,20.046 43.938,20.046 ; 43.739,20.046 43.938,20.046 ; 43.938,0.951 43.938,20.046 ; 43.938,0.951 43.938,20.046 ; 43.938,20.046 47.189,20.046 ; 47.189,20.046 47.189,27.4 32.189,27.4 32.189,-2.6 47.189,-2.6 47.189,20.046 ; -5.861,-3.6 11.139,-3.6 11.139,28.4 -5.861,28.4 -5.861,-3.6 ; 31.188,-3.6 31.188,28.4 48.189,28.4 48.189,-3.6 31.188,-3.6

## TX Antenna [mm] "TX 80 Ghz Antenna"
pads (6):
  round 0.25 smd: "D1 - TX1"(7.976,-0.25) "D1 - TX2"(4.058,-3.385) "D1 - TX3"(0.139,-0.25) "D2 - TX1"(29.527,-0.25) "D2 - TX2"(21.691,-0.25) "D2 - TX3"(13.854,-0.25)
Top Layer:
  region: 3.679,-3.743 3.919,-3.743 3.919,-3.135 4.196,-3.135 4.196,-4.535 4.108,-4.535 4.108,-5.735 4.307,-5.735 4.307,-6.835 4.108,-6.835 4.108,-8.035 4.507,-8.035 4.507,-9.12 4.108,-9.12 4.108,-10.32 4.657,-10.32 4.657,-11.39 4.108,-11.39 4.108,-12.59 4.808,-12.59 4.808,-13.65 4.108,-13.65 4.108,-14.85 4.808,-14.85 4.808,-15.91 4.108,-15.91 4.108,-17.11 4.657,-17.11 4.657,-18.18 4.108,-18.18 4.108,-19.38 4.507,-19.38 4.507,-20.465 4.108,-20.465 4.108,-21.665 4.307,-21.665 4.307,-22.765 3.808,-22.765 3.808,-21.665 4.008,-21.665 4.008,-20.465 3.608,-20.465 3.608,-19.38 4.008,-19.38 4.008,-18.18 3.458,-18.18 3.458,-17.11 4.008,-17.11 4.008,-15.91 3.307,-15.91 3.307,-14.85 4.008,-14.85 4.008,-13.65 3.307,-13.65 3.307,-12.59 4.008,-12.59 4.008,-11.39 3.458,-11.39 3.458,-10.32 4.008,-10.32 4.008,-9.12 3.608,-9.12 3.608,-8.035 4.008,-8.035 4.008,-6.835 3.808,-6.835 3.808,-5.735 4.008,-5.735 4.008,-4.535 3.919,-4.535 3.919,-4.02 3.679,-4.02
  region: 29.149,-0.608 29.389,-0.608 29.389,0 29.666,0 29.666,-1.4 29.577,-1.4 29.577,-2.6 29.777,-2.6 29.777,-3.7 29.577,-3.7 29.577,-4.9 29.977,-4.9 29.977,-5.985 29.577,-5.985 29.577,-7.185 30.127,-7.185 30.127,-8.255 29.577,-8.255 29.577,-9.455 30.278,-9.455 30.278,-10.515 29.577,-10.515 29.577,-11.715 30.278,-11.715 30.278,-12.775 29.577,-12.775 29.577,-13.975 30.127,-13.975 30.127,-15.045 29.577,-15.045 29.577,-16.245 29.977,-16.245 29.977,-17.33 29.577,-17.33 29.577,-18.53 29.777,-18.53 29.777,-19.63 29.278,-19.63 29.278,-18.53 29.478,-18.53 29.478,-17.33 29.078,-17.33 29.078,-16.245 29.478,-16.245 29.478,-15.045 28.928,-15.045 28.928,-13.975 29.478,-13.975 29.478,-12.775 28.777,-12.775 28.777,-11.715 29.478,-11.715 29.478,-10.515 28.777,-10.515 28.777,-9.455 29.478,-9.455 29.478,-8.255 28.928,-8.255 28.928,-7.185 29.478,-7.185 29.478,-5.985 29.078,-5.985 29.078,-4.9 29.478,-4.9 29.478,-3.7 29.278,-3.7 29.278,-2.6 29.478,-2.6 29.478,-1.4 29.389,-1.4 29.389,-0.885 29.149,-0.885
  region: 21.312,-0.608 21.552,-0.608 21.552,0 21.829,0 21.829,-1.4 21.741,-1.4 21.741,-2.6 21.94,-2.6 21.94,-3.7 21.741,-3.7 21.741,-4.9 22.14,-4.9 22.14,-5.985 21.741,-5.985 21.741,-7.185 22.29,-7.185 22.29,-8.255 21.741,-8.255 21.741,-9.455 22.441,-9.455 22.441,-10.515 21.741,-10.515 21.741,-11.715 22.441,-11.715 22.441,-12.775 21.741,-12.775 21.741,-13.975 22.29,-13.975 22.29,-15.045 21.741,-15.045 21.741,-16.245 22.14,-16.245 22.14,-17.33 21.741,-17.33 21.741,-18.53 21.94,-18.53 21.94,-19.63 21.441,-19.63 21.441,-18.53 21.641,-18.53 21.641,-17.33 21.241,-17.33 21.241,-16.245 21.641,-16.245 21.641,-15.045 21.091,-15.045 21.091,-13.975 21.641,-13.975 21.641,-12.775 20.94,-12.775 20.94,-11.715 21.641,-11.715 21.641,-10.515 20.94,-10.515 20.94,-9.455 21.641,-9.455 21.641,-8.255 21.091,-8.255 21.091,-7.185 21.641,-7.185 21.641,-5.985 21.241,-5.985 21.241,-4.9 21.641,-4.9 21.641,-3.7 21.441,-3.7 21.441,-2.6 21.641,-2.6 21.641,-1.4 21.552,-1.4 21.552,-0.885 21.312,-0.885
  region: 13.475,-0.608 13.715,-0.608 13.715,0 13.992,0 13.992,-1.4 13.904,-1.4 13.904,-2.6 14.103,-2.6 14.103,-3.7 13.904,-3.7 13.904,-4.9 14.303,-4.9 14.303,-5.985 13.904,-5.985 13.904,-7.185 14.453,-7.185 14.453,-8.255 13.904,-8.255 13.904,-9.455 14.604,-9.455 14.604,-10.515 13.904,-10.515 13.904,-11.715 14.604,-11.715 14.604,-12.775 13.904,-12.775 13.904,-13.975 14.453,-13.975 14.453,-15.045 13.904,-15.045 13.904,-16.245 14.303,-16.245 14.303,-17.33 13.904,-17.33 13.904,-18.53 14.103,-18.53 14.103,-19.63 13.604,-19.63 13.604,-18.53 13.804,-18.53 13.804,-17.33 13.404,-17.33 13.404,-16.245 13.804,-16.245 13.804,-15.045 13.254,-15.045 13.254,-13.975 13.804,-13.975 13.804,-12.775 13.103,-12.775 13.103,-11.715 13.804,-11.715 13.804,-10.515 13.103,-10.515 13.103,-9.455 13.804,-9.455 13.804,-8.255 13.254,-8.255 13.254,-7.185 13.804,-7.185 13.804,-5.985 13.404,-5.985 13.404,-4.9 13.804,-4.9 13.804,-3.7 13.604,-3.7 13.604,-2.6 13.804,-2.6 13.804,-1.4 13.715,-1.4 13.715,-0.885 13.475,-0.885
  region: 7.597,-0.608 7.837,-0.608 7.837,0 8.114,0 8.114,-1.4 8.026,-1.4 8.026,-2.6 8.226,-2.6 8.226,-3.7 8.026,-3.7 8.026,-4.9 8.426,-4.9 8.426,-5.985 8.026,-5.985 8.026,-7.185 8.575,-7.185 8.575,-8.255 8.026,-8.255 8.026,-9.455 8.726,-9.455 8.726,-10.515 8.026,-10.515 8.026,-11.715 8.726,-11.715 8.726,-12.775 8.026,-12.775 8.026,-13.975 8.575,-13.975 8.575,-15.045 8.026,-15.045 8.026,-16.245 8.426,-16.245 8.426,-17.33 8.026,-17.33 8.026,-18.53 8.226,-18.53 8.226,-19.63 7.726,-19.63 7.726,-18.53 7.926,-18.53 7.926,-17.33 7.526,-17.33 7.526,-16.245 7.926,-16.245 7.926,-15.045 7.376,-15.045 7.376,-13.975 7.926,-13.975 7.926,-12.775 7.225,-12.775 7.225,-11.715 7.926,-11.715 7.926,-10.515 7.225,-10.515 7.225,-9.455 7.926,-9.455 7.926,-8.255 7.376,-8.255 7.376,-7.185 7.926,-7.185 7.926,-5.985 7.526,-5.985 7.526,-4.9 7.926,-4.9 7.926,-3.7 7.726,-3.7 7.726,-2.6 7.926,-2.6 7.926,-1.4 7.837,-1.4 7.837,-0.885 7.597,-0.885
  region: -0.24,-0.608 0,-0.608 0,0 0.277,0 0.277,-1.4 0.189,-1.4 0.189,-2.6 0.389,-2.6 0.389,-3.7 0.189,-3.7 0.189,-4.9 0.589,-4.9 0.589,-5.985 0.189,-5.985 0.189,-7.185 0.738,-7.185 0.738,-8.255 0.189,-8.255 0.189,-9.455 0.889,-9.455 0.889,-10.515 0.189,-10.515 0.189,-11.715 0.889,-11.715 0.889,-12.775 0.189,-12.775 0.189,-13.975 0.738,-13.975 0.738,-15.045 0.189,-15.045 0.189,-16.245 0.589,-16.245 0.589,-17.33 0.189,-17.33 0.189,-18.53 0.389,-18.53 0.389,-19.63 -0.111,-19.63 -0.111,-18.53 0.089,-18.53 0.089,-17.33 -0.311,-17.33 -0.311,-16.245 0.089,-16.245 0.089,-15.045 -0.461,-15.045 -0.461,-13.975 0.089,-13.975 0.089,-12.775 -0.611,-12.775 -0.611,-11.715 0.089,-11.715 0.089,-10.515 -0.611,-10.515 -0.611,-9.455 0.089,-9.455 0.089,-8.255 -0.461,-8.255 -0.461,-7.185 0.089,-7.185 0.089,-5.985 -0.311,-5.985 -0.311,-4.9 0.089,-4.9 0.089,-3.7 -0.111,-3.7 -0.111,-2.6 0.089,-2.6 0.089,-1.4 0,-1.4 0,-0.885 -0.24,-0.885
Top Solder:
  region: -4.861,2.6 -4.861,-27.4 -0.943,-27.4 -0.943,-29.359 9.058,-29.359 9.058,-27.4 36.487,-27.4 36.487,2.6
Mechanical 2:
  drawing of 432 lines, arcs and shapes, not listed
Mechanical 5:
  lines w0.013: -4.861,-27.4 -4.861,2.6 ; -4.861,-27.4 5.139,-27.4 ; -4.861,-27.4 -4.861,2.6 ; -4.861,-27.4 5.139,-27.4 ; -4.861,2.6 5.139,2.6 ; -4.861,2.6 5.139,2.6 ; 2.976,-27.4 2.976,2.6 ; 2.976,-27.4 12.976,-27.4 ; 2.976,-27.4 2.976,2.6 ; 2.976,-27.4 12.976,-27.4 ; 2.976,2.6 12.976,2.6 ; 2.976,2.6 12.976,2.6 ; 5.139,-27.4 5.139,2.6 ; 5.139,-27.4 5.139,2.6 ; 12.976,-27.4 12.976,2.6 ; 12.976,-27.4 12.976,2.6 ; -0.943,-29.359 -0.943,0.641 9.058,0.641 9.058,-29.359 -0.943,-29.359 ; 8.854,-27.4 18.854,-27.4 18.854,2.6 8.854,2.6 8.854,-27.4 ; 16.691,-27.4 26.691,-27.4 26.691,2.6 16.691,2.6 16.691,-27.4 ; 24.527,-27.4 34.528,-27.4 34.528,2.6 24.527,2.6 24.527,-27.4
